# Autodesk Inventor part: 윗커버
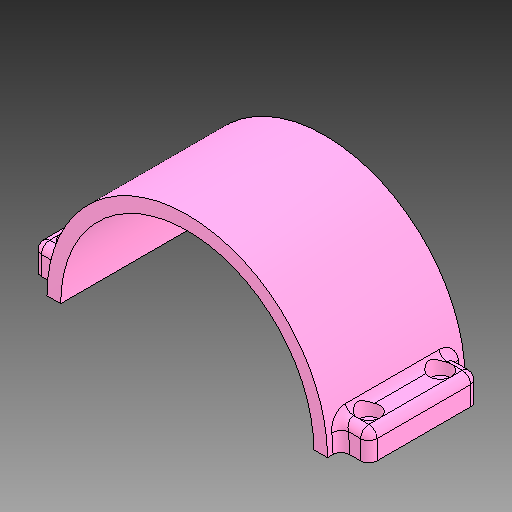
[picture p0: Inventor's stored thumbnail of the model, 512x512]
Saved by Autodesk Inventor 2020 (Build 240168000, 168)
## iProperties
Created: 2024-08
Part Number: 윗커버
Material: 알루미늄 6061
Document SubType Name: Modeling
Designer: 1강의실14
Density: 2.7 g/cm^3
Appearance: 기본값
Author: jhkim
Sending System: Autodesk Inventor 2025
Preprocessor: ST-DEVELOPER v20
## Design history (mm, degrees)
feature "솔리드1"
node "솔리드2"
